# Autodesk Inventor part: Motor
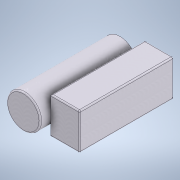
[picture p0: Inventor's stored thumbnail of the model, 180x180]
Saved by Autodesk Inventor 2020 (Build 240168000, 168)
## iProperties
Created: 2019-06
Part Number: Motor
Material: Aluminum 6061, Welded
Document SubType Name: Modeling
Designer: cl
Density: 2.7 g/cm^3
Appearance: Weld - Aluminum
Author: cl
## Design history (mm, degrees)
sketch "Sketch1"
  geometry: C1 r 65 at (0, 0); 1 further point
  constraints: 1 centre point, 1 coincident
  dimensions: "d0" = 130 diameter of C1
extrude "Extrusion1" new body sketch "Sketch1" distance "d1" = 370; taper "d2" = 0 deg
workplane "Work Plane1"
sketch "Sketch2"
  geometry: L1 (65, 70)-(175, 70); L2 (175, 70)-(175, -70); L3 (175, -70)-(65, -70); L4 (65, -70)-(65, 70); L5 (-65, 0)-(65, 0); L6 (65, 0)-(231.584, 0); C1 r 65 at (0, 0) reference; A1 r 65 centre (0, 0) between (-65, 0) and (65, 0) reference; 1 further point
  constraints: 12 end point, 2 horizontal, 2 parallel, 2 point on circle, 1 midpoint, 1 perpendicular, 1 point on line, 1 tangent
  dimensions: "d4" = 110 distance of L2.end L3.end; "d5" = 140 distance of L1.end L2.end; "d6" = 70 distance between parallel lines of L1 L6
extrude "Extrusion2" join sketch "Sketch2" distance "d7" = 360; taper "d8" = 0 deg
fillet "Fillet6" dims "d14" = 5
fillet "Fillet7" dims "d15" = 5
body "Solid1"
